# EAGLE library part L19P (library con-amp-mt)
AMP MT CONNECTOR
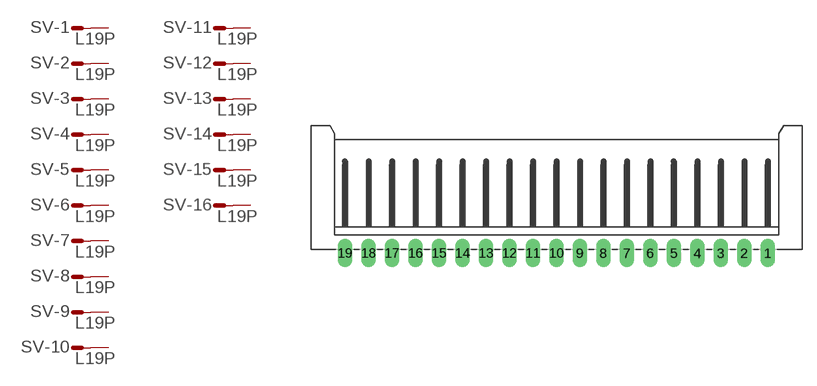
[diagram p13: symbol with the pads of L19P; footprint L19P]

Designator prefix SV; gates -1=M -2=M -3=M -4=M -5=M -6=M -7=M -8=M -9=M -10=M -11=M -12=M -13=M -14=M -15=M -16=M -17=M -18=M -19=M

## L19P (OC_FARNELL: unknown; OC_NEWARK: unknown)  [L19P]
1  -1:S  pas
2  -2:S  pas
3  -3:S  pas
4  -4:S  pas
5  -5:S  pas
6  -6:S  pas
7  -7:S  pas
8  -8:S  pas
9  -9:S  pas
10  -10:S  pas
11  -11:S  pas
12  -12:S  pas
13  -13:S  pas
14  -14:S  pas
15  -15:S  pas
16  -16:S  pas
17  -17:S  pas
18  -18:S  pas
19  -19:S  pas

## Footprint L19P (pad centres in mm)
AMP MT CONNECTOR
drill 1.016 long: 1 21.25,-6.25; 2 18.75,-6.25; 3 16.25,-6.25; 4 13.75,-6.25; 5 11.25,-6.25; 6 8.75,-6.25; 7 6.25,-6.25; 8 3.75,-6.25; 9 1.25,-6.25; 10 -1.25,-6.25; 11 -3.75,-6.25; 12 -6.25,-6.25; 13 -8.75,-6.25; 14 -11.25,-6.25; 15 -13.75,-6.25; 16 -16.24,-6.25; 17 -18.755,-6.25; 18 -21.244,-6.25; 19 -23.759,-6.25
